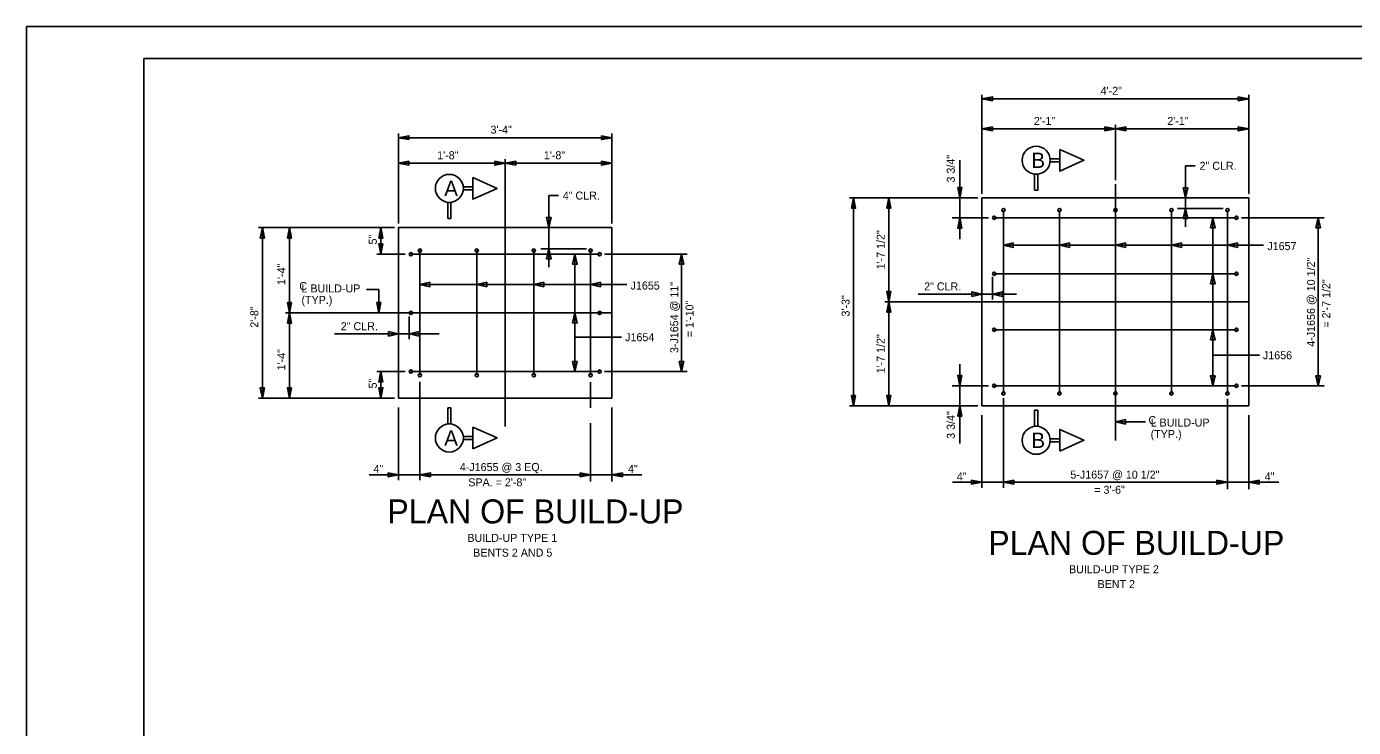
# Model space of a CAD drawing. Extents: x -133.1 to -97, y -1.7 to 20.3.
# Drawn here: x -133.14 to -112.41, y 9.36 to 20.31 of the extents above; entities that cross this region are included whole.
import ezdxf

# ---------------------------------------------------------------- set-up
doc = ezdxf.new("R2010")
doc.units = 0
for name, color, linetype in [('BR_AUTO DIMENSION', 7, 'Continuous'), ('BR_BORDER LINES', 7, 'Continuous'), ('BR_CENTER LINES', 7, 'Continuous'), ('BR_CONCRETE', 7, 'Continuous'), ('BR_REBAR', 7, 'Continuous'), ('BR_TEXT', 7, 'Continuous'), ('Level 31', 7, 'Continuous')]:
    doc.layers.add(name, color=color, linetype=linetype)

msp = doc.modelspace()

# ---------------------------------------------------------------- linework, layer by layer
at = {"layer": 'BR_AUTO DIMENSION'}
for p, q in [((-118.216, 17.695), (-118.216, 19.242)), ((-118.216, 19.179), (-114.049, 19.179)), ((-114.049, 17.695), (-114.049, 19.242)), ((-118.216, 18.708), (-116.132, 18.708)), ((-116.132, 17.908), (-116.132, 18.771)), ((-114.049, 18.708), (-116.132, 18.708)), ((-127.329, 17.229), (-127.329, 18.635)), ((-127.329, 18.572), (-123.996, 18.572)), ((-123.996, 17.229), (-123.996, 18.635)), ((-127.329, 18.172), (-125.662, 18.172)), ((-125.662, 17.229), (-125.662, 18.235)), ((-125.662, 18.172), (-123.996, 18.172)), ((-118.564, 16.984), (-118.564, 18.222)), ((-115.036, 17.178), (-115.036, 18.133)), ((-114.883, 18.133), (-115.036, 18.133)), ((-124.983, 16.546), (-124.983, 17.667)), ((-124.829, 17.667), (-124.983, 17.667)), ((-118.278, 17.632), (-120.284, 17.632)), ((-120.222, 14.382), (-120.222, 17.632)), ((-119.672, 16.007), (-119.672, 17.632)), ((-115.159, 17.466), (-114.446, 17.466)), ((-118.115, 17.32), (-118.682, 17.32)), ((-114.611, 17.32), (-114.611, 14.695)), ((-114.164, 17.32), (-112.872, 17.32)), ((-112.964, 14.695), (-112.964, 17.32)), ((-127.392, 17.167), (-129.52, 17.167)), ((-129.457, 17.167), (-129.457, 14.5)), ((-129.035, 17.167), (-129.035, 15.834)), ((-127.606, 17.167), (-127.606, 16.75)), ((-127.606, 17.167), (-127.606, 16.75)), ((-125.105, 16.834), (-124.393, 16.834)), ((-117.882, 16.894), (-113.817, 16.894)), ((-127.228, 16.75), (-127.669, 16.75)), ((-127.228, 16.75), (-127.669, 16.75)), ((-124.575, 16.75), (-124.575, 14.917)), ((-124.111, 16.75), (-122.819, 16.75)), ((-122.911, 14.917), (-122.911, 16.75)), ((-118.049, 16.4), (-118.049, 16.044)), ((-127.829, 16.201), (-127.637, 16.201)), ((-127.637, 16.201), (-127.637, 15.834)), ((-126.996, 16.278), (-123.764, 16.278)), ((-119.176, 16.007), (-119.735, 16.007)), ((-119.672, 14.382), (-119.672, 16.007)), ((-117.676, 16.128), (-119.215, 16.128)), ((-128.47, 15.834), (-129.098, 15.834)), ((-129.035, 14.5), (-129.035, 15.834)), ((-127.162, 15.778), (-127.162, 15.422)), ((-126.694, 15.506), (-128.328, 15.506)), ((-124.575, 15.456), (-123.846, 15.456)), ((-114.611, 15.174), (-113.883, 15.174)), ((-118.564, 15.031), (-118.564, 13.793)), ((-127.228, 14.917), (-127.669, 14.917)), ((-127.606, 14.5), (-127.606, 14.917)), ((-126.996, 14.755), (-126.996, 13.219)), ((-124.329, 14.751), (-124.329, 14.351)), ((-124.111, 14.917), (-122.819, 14.917)), ((-118.115, 14.695), (-118.682, 14.695)), ((-114.164, 14.695), (-112.872, 14.695)), ((-127.392, 14.5), (-129.52, 14.5)), ((-127.329, 14.356), (-127.329, 13.219)), ((-123.996, 14.356), (-123.996, 13.198)), ((-118.278, 14.382), (-120.284, 14.382)), ((-117.882, 14.499), (-117.882, 13.101)), ((-114.382, 14.49), (-114.382, 13.08)), ((-124.329, 14.109), (-124.329, 13.198)), ((-118.216, 14.238), (-118.216, 13.101)), ((-116.132, 14.131), (-115.661, 14.131)), ((-114.049, 14.238), (-114.049, 13.08)), ((-126.996, 13.305), (-127.789, 13.305)), ((-126.996, 13.305), (-124.329, 13.305)), ((-124.329, 13.305), (-123.527, 13.305)), ((-117.882, 13.187), (-118.675, 13.187)), ((-117.882, 13.187), (-114.382, 13.187)), ((-114.382, 13.187), (-113.581, 13.187))]:
    msp.add_line(p, q, dxfattribs=at)
for points in [[(-118.053, 19.148), (-118.216, 19.179), (-118.053, 19.211)], [(-114.212, 19.211), (-114.049, 19.179), (-114.212, 19.148)], [(-118.053, 18.677), (-118.216, 18.708), (-118.053, 18.74)], [(-116.295, 18.74), (-116.132, 18.708), (-116.295, 18.677)], [(-115.97, 18.677), (-116.132, 18.708), (-115.97, 18.74)], [(-114.212, 18.74), (-114.049, 18.708), (-114.212, 18.677)], [(-127.167, 18.541), (-127.329, 18.572), (-127.167, 18.603)], [(-124.158, 18.603), (-123.996, 18.572), (-124.158, 18.541)], [(-127.167, 18.141), (-127.329, 18.172), (-127.167, 18.204)], [(-125.825, 18.204), (-125.662, 18.172), (-125.825, 18.141)], [(-125.5, 18.141), (-125.662, 18.172), (-125.5, 18.204)], [(-124.158, 18.204), (-123.996, 18.172), (-124.158, 18.141)], [(-120.253, 17.47), (-120.222, 17.632), (-120.19, 17.47)], [(-119.703, 17.47), (-119.672, 17.632), (-119.641, 17.47)], [(-118.595, 17.795), (-118.564, 17.632), (-118.532, 17.795)], [(-115, 17.788), (-115.036, 17.632), (-115.072, 17.788)], [(-115.072, 17.31), (-115.036, 17.466), (-115, 17.31)], [(-124.947, 17.323), (-124.983, 17.167), (-125.019, 17.323)], [(-118.532, 17.157), (-118.564, 17.32), (-118.595, 17.157)], [(-114.647, 17.164), (-114.611, 17.32), (-114.575, 17.164)], [(-113, 17.164), (-112.964, 17.32), (-112.928, 17.164)], [(-129.489, 17.004), (-129.457, 17.167), (-129.426, 17.004)], [(-129.066, 17.004), (-129.035, 17.167), (-129.004, 17.004)], [(-127.638, 17.004), (-127.606, 17.167), (-127.575, 17.004)], [(-127.638, 17.004), (-127.606, 17.167), (-127.575, 17.004)], [(-127.575, 16.913), (-127.606, 16.75), (-127.638, 16.913)], [(-127.575, 16.913), (-127.606, 16.75), (-127.638, 16.913)], [(-125.019, 16.678), (-124.983, 16.834), (-124.947, 16.678)], [(-117.726, 16.93), (-117.882, 16.894), (-117.726, 16.858)], [(-116.851, 16.93), (-117.007, 16.894), (-116.851, 16.858)], [(-115.976, 16.93), (-116.132, 16.894), (-115.976, 16.858)], [(-115.101, 16.93), (-115.257, 16.894), (-115.101, 16.858)], [(-114.226, 16.93), (-114.382, 16.894), (-114.226, 16.858)], [(-124.611, 16.594), (-124.575, 16.75), (-124.539, 16.594)], [(-122.947, 16.594), (-122.911, 16.75), (-122.875, 16.594)], [(-114.647, 16.289), (-114.611, 16.445), (-114.575, 16.289)], [(-126.84, 16.314), (-126.996, 16.278), (-126.84, 16.242)], [(-125.951, 16.314), (-126.107, 16.278), (-125.951, 16.242)], [(-125.062, 16.314), (-125.218, 16.278), (-125.062, 16.242)], [(-124.173, 16.314), (-124.329, 16.278), (-124.173, 16.242)], [(-119.641, 16.17), (-119.672, 16.007), (-119.703, 16.17)], [(-129.004, 15.996), (-129.035, 15.834), (-129.066, 15.996)], [(-127.606, 15.996), (-127.637, 15.834), (-127.669, 15.996)], [(-119.703, 15.845), (-119.672, 16.007), (-119.641, 15.845)], [(-118.372, 16.092), (-118.216, 16.128), (-118.372, 16.164)], [(-117.893, 16.164), (-118.049, 16.128), (-117.893, 16.092)], [(-129.066, 15.671), (-129.035, 15.834), (-129.004, 15.671)], [(-124.611, 15.678), (-124.575, 15.834), (-124.539, 15.678)], [(-114.647, 15.414), (-114.611, 15.57), (-114.575, 15.414)], [(-127.485, 15.47), (-127.329, 15.506), (-127.485, 15.542)], [(-127.006, 15.542), (-127.162, 15.506), (-127.006, 15.47)], [(-124.539, 15.073), (-124.575, 14.917), (-124.611, 15.073)], [(-122.875, 15.073), (-122.911, 14.917), (-122.947, 15.073)], [(-127.575, 14.754), (-127.606, 14.917), (-127.638, 14.754)], [(-118.532, 14.857), (-118.564, 14.695), (-118.595, 14.857)], [(-114.575, 14.851), (-114.611, 14.695), (-114.647, 14.851)], [(-112.928, 14.851), (-112.964, 14.695), (-113, 14.851)], [(-129.426, 14.663), (-129.457, 14.5), (-129.489, 14.663)], [(-129.004, 14.663), (-129.035, 14.5), (-129.066, 14.663)], [(-127.638, 14.663), (-127.606, 14.5), (-127.575, 14.663)], [(-120.19, 14.545), (-120.222, 14.382), (-120.253, 14.545)], [(-119.641, 14.545), (-119.672, 14.382), (-119.703, 14.545)], [(-118.595, 14.22), (-118.564, 14.382), (-118.532, 14.22)], [(-115.976, 14.095), (-116.132, 14.131), (-115.976, 14.167)], [(-127.492, 13.336), (-127.329, 13.305), (-127.492, 13.273)], [(-126.833, 13.273), (-126.996, 13.305), (-126.833, 13.336)], [(-124.492, 13.336), (-124.329, 13.305), (-124.492, 13.273)], [(-123.833, 13.336), (-123.996, 13.305), (-123.833, 13.273)], [(-118.378, 13.218), (-118.216, 13.187), (-118.378, 13.155)], [(-117.72, 13.155), (-117.882, 13.187), (-117.72, 13.218)], [(-114.545, 13.218), (-114.382, 13.187), (-114.545, 13.155)], [(-113.887, 13.218), (-114.049, 13.187), (-113.887, 13.155)]]:
    msp.add_lwpolyline(points, close=True, dxfattribs=at)
at = {"layer": 'BR_BORDER LINES'}
for p in [(-97.642, 19.809), (-131.308, -1.191)]:
    msp.add_line(p, (-131.308, 19.809), dxfattribs=at)
at = {"layer": 'BR_CENTER LINES'}
for p, q in [((-116.132, 13.84), (-116.132, 17.846)), ((-125.662, 14.058), (-125.662, 17.681)), ((-114.049, 16.007), (-119.186, 16.007)), ((-123.996, 15.834), (-128.667, 15.834))]:
    msp.add_line(p, q, dxfattribs=at)
at = {"layer": 'BR_CONCRETE'}
for p, q in [((-118.216, 17.632), (-118.216, 14.382)), ((-118.216, 17.632), (-114.049, 17.632)), ((-114.049, 17.632), (-114.049, 14.382)), ((-127.329, 14.5), (-127.329, 17.167)), ((-123.996, 17.167), (-127.329, 17.167)), ((-123.996, 14.5), (-123.996, 17.167)), ((-127.329, 14.5), (-123.996, 14.5)), ((-114.049, 14.382), (-118.216, 14.382))]:
    msp.add_line(p, q, dxfattribs=at)
at = {"layer": 'BR_REBAR'}
for p, q in [((-117.882, 14.575), (-117.882, 17.44)), ((-117.007, 14.575), (-117.007, 17.44)), ((-116.132, 14.575), (-116.132, 17.44)), ((-115.257, 14.575), (-115.257, 17.44)), ((-114.382, 14.575), (-114.382, 17.44)), ((-118.023, 17.32), (-114.242, 17.32)), ((-126.996, 14.86), (-126.996, 16.808)), ((-126.107, 14.86), (-126.107, 16.808)), ((-125.218, 14.86), (-125.218, 16.808)), ((-124.329, 14.86), (-124.329, 16.808)), ((-127.136, 16.75), (-124.188, 16.75)), ((-118.023, 16.445), (-114.242, 16.445)), ((-127.136, 15.834), (-124.188, 15.834)), ((-118.023, 15.57), (-114.242, 15.57)), ((-127.136, 14.917), (-124.188, 14.917)), ((-118.023, 14.695), (-114.242, 14.695))]:
    msp.add_line(p, q, dxfattribs=at)
for centre, radius in [((-117.882, 17.44), 0.026), ((-117.007, 17.44), 0.026), ((-116.132, 17.44), 0.026), ((-115.257, 17.44), 0.026), ((-114.382, 17.44), 0.026), ((-118.023, 17.32), 0.0261), ((-114.242, 17.32), 0.0261), ((-126.996, 16.808), 0.026), ((-126.107, 16.808), 0.026), ((-125.218, 16.808), 0.026), ((-124.329, 16.808), 0.026), ((-127.136, 16.75), 0.026), ((-124.188, 16.75), 0.026), ((-118.023, 16.445), 0.0261), ((-114.242, 16.445), 0.0261), ((-127.136, 15.834), 0.026), ((-124.188, 15.834), 0.026), ((-118.023, 15.57), 0.0261), ((-114.242, 15.57), 0.0261), ((-127.136, 14.917), 0.026), ((-124.188, 14.917), 0.026), ((-126.996, 14.86), 0.026), ((-126.107, 14.86), 0.026), ((-125.218, 14.86), 0.026), ((-124.329, 14.86), 0.026), ((-118.023, 14.695), 0.0261), ((-114.242, 14.695), 0.0261), ((-117.882, 14.575), 0.026), ((-117.007, 14.575), 0.026), ((-116.132, 14.575), 0.026), ((-115.257, 14.575), 0.026), ((-114.382, 14.575), 0.026)]:
    msp.add_circle(centre, radius, dxfattribs=at)
at = {"layer": 'BR_TEXT'}
for points in [[(-117.15, 18.194), (-117, 18.194), (-117, 18.244), (-117.15, 18.244)], [(-117, 18.388), (-116.624, 18.219), (-117, 18.05)], [(-126.167, 17.949), (-125.791, 17.78), (-126.167, 17.611)], [(-117.394, 17.75), (-117.344, 17.75), (-117.344, 18), (-117.394, 18)], [(-126.317, 17.755), (-126.167, 17.755), (-126.167, 17.805), (-126.317, 17.805)], [(-126.561, 17.311), (-126.511, 17.311), (-126.511, 17.561), (-126.561, 17.561)], [(-126.561, 14.348), (-126.511, 14.348), (-126.511, 14.098), (-126.561, 14.098)], [(-117.394, 14.312), (-117.344, 14.312), (-117.344, 14.062), (-117.394, 14.062)], [(-126.317, 13.904), (-126.167, 13.904), (-126.167, 13.854), (-126.317, 13.854)], [(-126.167, 13.71), (-125.791, 13.879), (-126.167, 14.048)], [(-117, 13.674), (-116.624, 13.843), (-117, 14.012)], [(-117.15, 13.868), (-117, 13.868), (-117, 13.818), (-117.15, 13.818)]]:
    msp.add_lwpolyline(points, close=True, dxfattribs=at)
for centre in [(-117.369, 18.219), (-126.536, 17.78), (-126.536, 13.879), (-117.369, 13.843)]:
    msp.add_circle(centre, 0.219, dxfattribs=at)
at = {"layer": 'Level 31'}
msp.add_lwpolyline([(-133.141, -1.691), (-97.141, -1.691), (-97.141, 20.309), (-133.141, 20.309)], close=True, dxfattribs=at)

# ---------------------------------------------------------------- texts
at = {"layer": 'BR_AUTO DIMENSION'}
for s, p in [('4\'-2"', (-116.363, 19.242)), ('2\'-1"', (-117.405, 18.771)), ('2\'-1"', (-115.321, 18.771)), ('3\'-4"', (-125.893, 18.635)), ('1\'-8"', (-126.726, 18.235)), ('1\'-8"', (-125.06, 18.235)), ('2" CLR.', (-114.817, 18.07)), ('4" CLR.', (-124.764, 17.605)), ('J1657', (-113.758, 16.815)), ('C', (-128.88, 16.191)), ('L BUILD-UP', (-128.846, 16.154)), ('J1655', (-123.705, 16.199)), ('2" CLR.', (-119.119, 16.185)), ('(TYP.)', (-128.846, 15.974)), ('2" CLR.', (-128.232, 15.563)), ('J1654', (-123.79, 15.391)), ('J1656', (-113.827, 15.109)), ('C', (-115.615, 14.095)), ('L BUILD-UP', (-115.581, 14.058)), ('(TYP.)', (-115.581, 13.878)), ('4-J1655 @ 3 EQ.', (-126.373, 13.362)), ('4"', (-127.721, 13.333)), ('4"', (-123.746, 13.333)), ('4"', (-118.608, 13.215)), ('5-J1657 @ 10 1/2"', (-116.835, 13.244)), ('4"', (-113.799, 13.215)), ('SPA. = 2\'-8"', (-126.24, 13.124)), ('= 3\'-6"', (-116.462, 13.007)), ('BUILD-UP TYPE 1', (-126.254, 12.256)), ('BENTS 2 AND 5', (-126.163, 12.025)), ('BUILD-UP TYPE 2', (-116.856, 11.765)), ('BENT 2', (-116.41, 11.534))]:
    msp.add_text(s, height=0.125, dxfattribs=at).set_placement(p)
for s, p in [('3 3/4"', (-118.64, 17.871)), ('5"', (-127.669, 16.903)), ('1\'-7 1/2"', (-119.735, 16.514)), ('1\'-4"', (-129.098, 16.27)), ('4-J1656 @ 10 1/2"', (-113.013, 15.305)), ('3-J1654 @ 11"', (-122.96, 15.206)), ('= 2\'-7 1/2"', (-112.776, 15.603)), ('= 1\'-10"', (-122.722, 15.454)), ('3\'-3"', (-120.284, 15.777)), ('2\'-8"', (-129.52, 15.603)), ('1\'-7 1/2"', (-119.735, 14.889)), ('1\'-4"', (-129.098, 14.936)), ('5"', (-127.669, 14.653)), ('3 3/4"', (-118.64, 13.866))]:
    msp.add_text(s, height=0.125, rotation=90, dxfattribs=at).set_placement(p)
at = {"layer": 'BR_TEXT'}
for s, height, p in [('B', 0.24, (-117.444, 18.099)), ('A', 0.24, (-126.616, 17.66)), ('A', 0.24, (-126.616, 13.759)), ('B', 0.24, (-117.444, 13.723)), ('PLAN OF BUILD-UP', 0.375, (-127.504, 12.544)), ('PLAN OF BUILD-UP', 0.375, (-118.118, 12.053))]:
    msp.add_text(s, height=height, dxfattribs=at).set_placement(p)

doc.saveas('drawing.dxf')
